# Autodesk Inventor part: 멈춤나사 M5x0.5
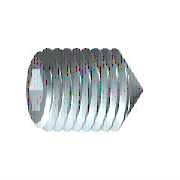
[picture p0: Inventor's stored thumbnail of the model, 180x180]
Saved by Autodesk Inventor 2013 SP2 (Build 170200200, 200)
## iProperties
Company: 한국ATC센터
IsCustomPart: 1
Created: 2014-11
Part Number: 멈춤나사 M5x0.5
Material: 강, 연강
Description: 6각 소켓 머리 없는 멈춤 나사
Document SubType Name: Modeling
Standard: KS B 1028
Designer: KYOUNG IL JANG
Standards Organization: KS
Language: ko-KR
Size Designation: 원추점 M5x10
Categories: <MemberInstance><Categories><Category DisplayName="조임쇠" InternalName="e4da775c-781d-43d5-af7c-5136215cf5a6" Mnemonic="FSTN"><Category DisplayName="볼트" InternalN
Density: 7.86 g/cm^3
Mass: 1.16912 g
Surface Area: 1.91683 cm^2
Volume: 0.148743 cm^3
Author: KYOUNG IL JANG
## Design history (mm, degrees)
sketch "스케치1"
  geometry: L1 (0, 0)-(6.167, 0); L2 (10, 1.443)-(10, 2.5); L3 (10, 2.5)-(0, 2.5); L4 (10, 1.443)-(7, 1.443); L5 (7, 1.443)-(6.167, 0); L6 (0, -0.5)-(0, 3) reference; L7 (0, 2.5)-(0, 0)
  constraints: 13 end point, 3 parallel, 1 collinear, 1 perpendicular, 1 point on line
  dimensions: "d0" = 3 distance of L2.start L4.end (= INTI); "d1" = 60 deg angle of L5 L1; "d2" = 5 diameter of L3 L1 (= NND); "d3" = 2.88675 diameter of L4 L1 (= 1.1547 x SW); "d5" = 10 distance from line of L2 L3.end (= NLG)
revolve "본체" sketch "스케치1" stored, may be unused: angle "d6" = 90 deg
sketch "스케치2"
  geometry: L1 (-0.722, 1.25)-(0.722, 1.25); L2 (0.722, 1.25)-(1.443, 0); L3 (1.443, 0)-(0.722, -1.25); L4 (0.722, -1.25)-(-0.722, -1.25); L5 (-0.722, -1.25)-(-1.443, 0); L6 (-1.443, 0)-(-0.722, 1.25); 3 further points
  constraints: 12 end point, 1 coincident, 1 horizontal, 13 other
extrude "슬롯" join sketch "스케치2" taper "d7" = 0 deg; stored distance "d21" = 10
workaxis "Work Axis1"
workplane "Work Plane1"
body "Solid1"
feature "스레드" dims "d12" = 10 (= NLG), "d13" = 0
chamfer "모따기1" distance "d8" = 2.25 (computed from NND, SPD, FAWI); stored, may be unused: angle "d9" = 45 deg (= FAWI), second distance "d34" = 2.25 (computed from NND, SPD, FAWI)
chamfer "모따기2" distance "d10" = 0.49076 (= -0.5 x GD1 + 0.5 x NND); stored, may be unused: angle "d11" = 45 deg (= FAWI), second distance "d35" = 0.49076 (= -0.5 x GD1 + 0.5 x NND)
other parameters: "NND" = 5 [user parameter; used in 5 equation terms], "NLG" = 10 [user parameter; used in 2 equation terms], "INTI" = 3 [user parameter; used in 1 equation term], "FAWI" = 45 deg [user parameter; used in 4 equation terms], "SW" = 2.5 [user parameter; used in 2 equation terms], "GD1" = 4.01848 (= THREADDIA - 1.2269 x PTC) [user parameter; used in 2 equation terms], "d4" = 0, "FAWI1" = 45 deg [user parameter], "SPD" = 0.5 [user parameter; used in 2 equation terms], "d36" = 0, "d37" = 0, "GUL" = 0.49076 (= 0.61345 x PTC) [user parameter], "TPU" = 12.5 (computed from PTC) [user parameter], "TOA" = 30 deg [user parameter], "THREADDIA" = 5 [user parameter; used in 1 equation term], "PTC" = 0.8 [user parameter; used in 4 equation terms], "GAL" = 0.49076 (= 0.61345 x PTC) [user parameter], "E0" = 2.8875 (= 1.155 x SW) [user parameter]
